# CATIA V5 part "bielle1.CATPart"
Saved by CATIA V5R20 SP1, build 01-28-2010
Part number: bielle3
Bounding box of the stored display mesh (mm): x 17.186 to 85.829, y -10 to 5, z 29.034 to 40.966
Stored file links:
  E:\EDELI\gcausse\Edeli_2012_681_gcausse\bielle1.CATPart
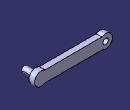
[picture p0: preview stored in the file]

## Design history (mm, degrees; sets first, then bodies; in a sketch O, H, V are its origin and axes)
Parameters
  long = 0.0569853
  diamtrou = 0.005
Body1 (main body)
  Sketch1 on zx-plane, origin (0, 0, 0), H (-1, 0, 0), V (0, 0, 1)
    line L1 (-26.3313, 40) -> (-76.6834, 40)
    line L2 (-26.3313, 30) -> (-76.6834, 30)
    arc A1 centre (-23.0147, 35) radius 6 from (-26.3313, 40) to (-26.3313, 30) cw
    point P5 (-23.0147, 35)
    point P6 (-19.6981, 30)
    arc A2 centre (-80, 35) radius 6 from (-76.6834, 40) to (-76.6834, 30) ccw
    point P7 (-80, 35)
    circle A3 centre (-23.0147, 35) radius 2.5
    distance P7 L1 = 5
    distance P5 L2 = 5
    distance L2 L1 = 10
    radius A1 = 6
    radius A2 = 6
    distance P5 P7 = 56.9853 {= long}
    radius A3 = 2.5
    horizontal: L1 H, L2 H
    coincidence: A1 P6, P6 L2
  Pad1: profile Sketch1, direction (0, 1, 0), length 5
  Sketch2 on start face of Pad1, origin (0, 0, 0), H (1, 0, 0), V (0, 0, 1)
    circle A1 centre (80, 35) radius 2.5
    reference projected arc E1 centre (80, 35) radius 6 from (75.8009, 30.7143) to (75.8009, 39.2857) ccw from edge [start face of Pad1 | face of Pad1 from Sketch1.A2]
    reference projected arc E2 centre (80, 35) radius 6 from (75.8009, 30.7143) to (75.8009, 39.2857) ccw from edge [start face of Pad1 | face of Pad1 from Sketch1.A2]
    radius A1 = 2.5
    radius E2 = 6 (reference)
    concentricity: A1 E1
  Pad2: profile Sketch2, direction (0, -1, 0), length 10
